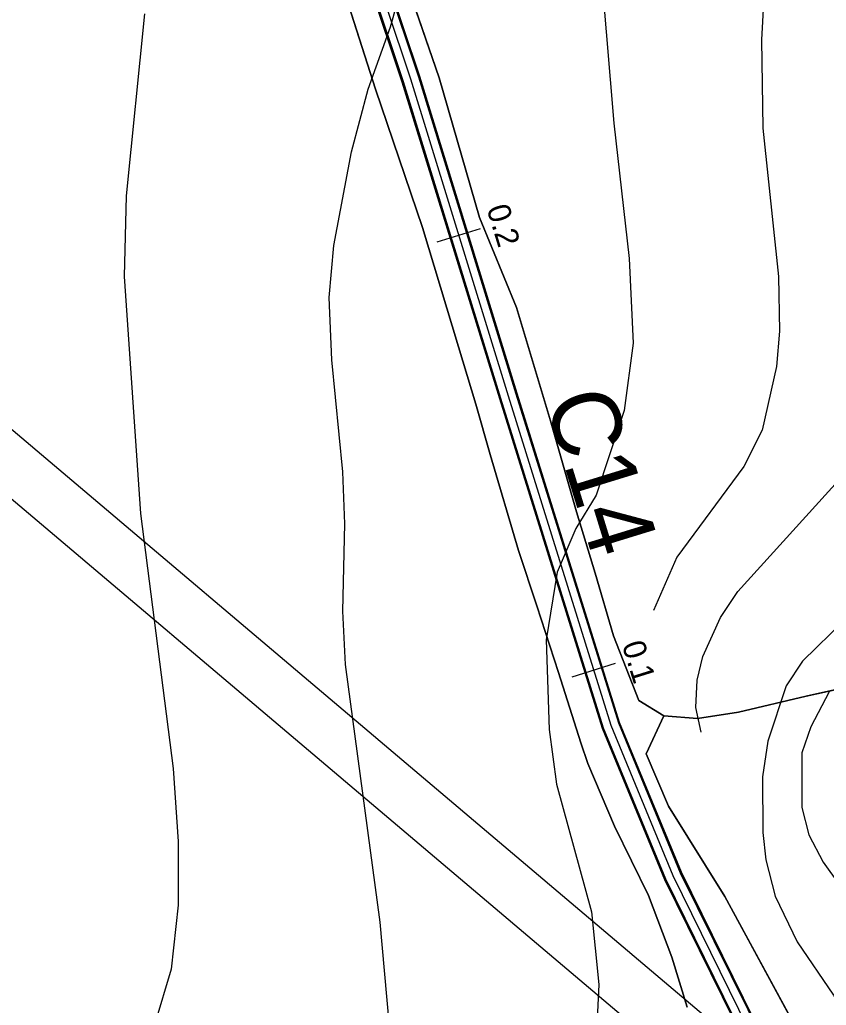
# Model space of a CAD drawing. Extents: x -662620 to -656370, y -1067090 to -1062990.
# Drawn here: x -660708.3 to -660531.2, y -1064020.6 to -1063804.1 of the extents above; entities that cross this region are included whole.
import ezdxf

# ---------------------------------------------------------------- set-up
doc = ezdxf.new("R2010")
doc.units = 0
for name, color, linetype in [('CESTA_ZABOR', 7, 'Continuous'), ('Default', 7, 'Continuous'), ('ELEK__VEDENÍ_VN_-_NADZEMNÍ', 7, 'Continuous'), ('ELEK__VEDENÍ_VVN_-_NADZEMNÍ', 7, 'Continuous'), ('ORNÁ_PŮDA_-_STÁVAJÍCÍ', 7, 'Continuous'), ('OSTATNÍ_PLOCHA_-_STÁVAJÍCÍ', 7, 'Continuous'), ('POLNÍ_CESTA_STÁVAJÍCÍ_-_KRAJ', 7, 'Continuous'), ('POLNÍ_CESTA_STÁVAJÍCÍ_-_OSA', 7, 'Continuous'), ('Popis_objektů_polních_cest_stávajících', 7, 'Continuous'), ('Trvalý_trávní_porost_-_stávající', 7, 'Continuous'), ('VRSTEVNICE_ZDŮRAZNĚNÁ', 7, 'Continuous'), ('VRSTEVNICE_ZÁKLADNÍ', 7, 'Continuous')]:
    doc.layers.add(name, color=color, linetype=linetype)

msp = doc.modelspace()

# ---------------------------------------------------------------- linework, layer by layer
at = {"layer": 'CESTA_ZABOR'}
for points in [[(-660641.89, -1063753.33), (-660620.72, -1063816.66), (-660599.33, -1063886.28), (-660576.8, -1063958.52), (-660563.25, -1063991.45), (-660541, -1064036.4), (-660545.17, -1064036.09), (-660566.44, -1063992.89), (-660580.1, -1063959.71), (-660602.67, -1063887.31), (-660624.05, -1063817.73), (-660645.21, -1063754.44), (-660641.89, -1063753.33), (-660641.89, -1063753.33)], [(-660641.89, -1063753.33), (-660620.72, -1063816.66), (-660599.33, -1063886.28), (-660576.8, -1063958.52), (-660563.25, -1063991.45), (-660541, -1064036.4), (-660545.17, -1064036.09), (-660566.44, -1063992.89), (-660580.1, -1063959.71), (-660602.67, -1063887.31), (-660624.05, -1063817.73), (-660645.21, -1063754.44)]]:
    msp.add_lwpolyline(points, dxfattribs=at)
at = {"layer": 'ELEK__VEDENÍ_VN_-_NADZEMNÍ'}
for points in [[(-660826.12, -1063795.76), (-660509.03, -1064064.22)], [(-660516.66, -1064073.17), (-660833.72, -1063804.76)]]:
    msp.add_lwpolyline(points, dxfattribs=at)
at = {"layer": 'ELEK__VEDENÍ_VVN_-_NADZEMNÍ'}
for points in [[(-661103.94, -1063560.48), (-660826.12, -1063795.76), (-660509.03, -1064064.22)], [(-659212.59, -1064402.76), (-659241.86, -1064399.78), (-659588.53, -1064364.37), (-659927.91, -1064329.98), (-660254.66, -1064303.24), (-660516.66, -1064073.17), (-660833.72, -1063804.76), (-661111.8, -1063569.65)]]:
    msp.add_lwpolyline(points, dxfattribs=at)
at = {"layer": 'ORNÁ_PŮDA_-_STÁVAJÍCÍ'}
for p, q in [((-660638.5, -1063793.19), (-660630.18, -1063819.37)), ((-660616.18, -1063816.87), (-660624.82, -1063791.76)), ((-660607.35, -1063847.54), (-660616.18, -1063816.87)), ((-660630.18, -1063819.37), (-660619.87, -1063849.72)), ((-660599.2, -1063867.29), (-660607.35, -1063847.54)), ((-660619.87, -1063849.72), (-660611.93, -1063875.98)), ((-660591.78, -1063892.18), (-660599.2, -1063867.29)), ((-660611.93, -1063875.98), (-660608.12, -1063888.55)), ((-660608.12, -1063888.55), (-660604.99, -1063899.59)), ((-660586.04, -1063912.22), (-660591.78, -1063892.18)), ((-660604.99, -1063899.59), (-660598.8, -1063920.65)), ((-660581.92, -1063925.63), (-660586.04, -1063912.22)), ((-660598.8, -1063920.65), (-660594.78, -1063932.87)), ((-660577.93, -1063939.44), (-660581.92, -1063925.63)), ((-660594.78, -1063932.87), (-660589.98, -1063947.47)), ((-660572.35, -1063953.64), (-660577.93, -1063939.44)), ((-660589.98, -1063947.47), (-660585.11, -1063962.91)), ((-660521.18, -1063949.49), (-660535.62, -1063952.7)), ((-660566.85, -1063957.02), (-660572.35, -1063953.64)), ((-660535.62, -1063952.7), (-660550.46, -1063956.21)), ((-660559.46, -1063957.55), (-660566.85, -1063957.02)), ((-660550.46, -1063956.21), (-660559.46, -1063957.55)), ((-660585.11, -1063962.91), (-660583.57, -1063967.48)), ((-660583.57, -1063967.48), (-660577.71, -1063981.23)), ((-660577.71, -1063981.23), (-660570.22, -1063996.43)), ((-660570.22, -1063996.43), (-660565.08, -1064009.97)), ((-660565.08, -1064009.97), (-660561.74, -1064020.99))]:
    msp.add_line(p, q, dxfattribs=at)
for points in [[(-660638.5, -1063793.19), (-660630.18, -1063819.37), (-660619.87, -1063849.72), (-660611.93, -1063875.98), (-660608.12, -1063888.55), (-660604.99, -1063899.59), (-660598.8, -1063920.65), (-660594.78, -1063932.87), (-660589.98, -1063947.47), (-660585.11, -1063962.91), (-660583.57, -1063967.48), (-660577.71, -1063981.23), (-660570.22, -1063996.43), (-660565.08, -1064009.97), (-660561.74, -1064020.99)], [(-660521.18, -1063949.49), (-660535.62, -1063952.7), (-660550.46, -1063956.21), (-660559.46, -1063957.55), (-660566.85, -1063957.02), (-660572.35, -1063953.64), (-660577.93, -1063939.44), (-660581.92, -1063925.63), (-660586.04, -1063912.22), (-660591.78, -1063892.18), (-660599.2, -1063867.29), (-660607.35, -1063847.54), (-660616.18, -1063816.87), (-660624.82, -1063791.76)]]:
    msp.add_lwpolyline(points, dxfattribs=at)
at = {"layer": 'OSTATNÍ_PLOCHA_-_STÁVAJÍCÍ'}
for p, q in [((-660630.18, -1063819.37), (-660638.5, -1063793.19)), ((-660630.18, -1063819.37), (-660638.5, -1063793.19)), ((-660624.82, -1063791.76), (-660616.18, -1063816.87)), ((-660624.82, -1063791.76), (-660616.18, -1063816.87)), ((-660616.18, -1063816.87), (-660607.35, -1063847.54)), ((-660616.18, -1063816.87), (-660607.35, -1063847.54)), ((-660619.87, -1063849.72), (-660630.18, -1063819.37)), ((-660619.87, -1063849.72), (-660630.18, -1063819.37)), ((-660607.35, -1063847.54), (-660599.2, -1063867.29)), ((-660607.35, -1063847.54), (-660599.2, -1063867.29)), ((-660611.93, -1063875.98), (-660619.87, -1063849.72)), ((-660611.93, -1063875.98), (-660619.87, -1063849.72)), ((-660599.2, -1063867.29), (-660591.78, -1063892.18)), ((-660599.2, -1063867.29), (-660591.78, -1063892.18)), ((-660608.12, -1063888.55), (-660611.93, -1063875.98)), ((-660608.12, -1063888.55), (-660611.93, -1063875.98)), ((-660604.99, -1063899.59), (-660608.12, -1063888.55)), ((-660604.99, -1063899.59), (-660608.12, -1063888.55)), ((-660591.78, -1063892.18), (-660586.04, -1063912.22)), ((-660591.78, -1063892.18), (-660586.04, -1063912.22)), ((-660598.8, -1063920.65), (-660604.99, -1063899.59)), ((-660598.8, -1063920.65), (-660604.99, -1063899.59)), ((-660586.04, -1063912.22), (-660581.92, -1063925.63)), ((-660586.04, -1063912.22), (-660581.92, -1063925.63)), ((-660594.78, -1063932.87), (-660598.8, -1063920.65)), ((-660594.78, -1063932.87), (-660598.8, -1063920.65)), ((-660581.92, -1063925.63), (-660577.93, -1063939.44)), ((-660581.92, -1063925.63), (-660577.93, -1063939.44)), ((-660589.98, -1063947.47), (-660594.78, -1063932.87)), ((-660589.98, -1063947.47), (-660594.78, -1063932.87)), ((-660577.93, -1063939.44), (-660572.35, -1063953.64)), ((-660577.93, -1063939.44), (-660572.35, -1063953.64)), ((-660585.11, -1063962.91), (-660589.98, -1063947.47)), ((-660585.11, -1063962.91), (-660589.98, -1063947.47)), ((-660572.35, -1063953.64), (-660566.85, -1063957.02)), ((-660572.35, -1063953.64), (-660566.85, -1063957.02)), ((-660566.85, -1063957.02), (-660570.78, -1063965.32)), ((-660566.85, -1063957.02), (-660570.78, -1063965.32)), ((-660583.57, -1063967.48), (-660585.11, -1063962.91)), ((-660583.57, -1063967.48), (-660585.11, -1063962.91)), ((-660570.78, -1063965.32), (-660565.86, -1063976.81)), ((-660570.78, -1063965.32), (-660565.86, -1063976.81)), ((-660577.71, -1063981.23), (-660583.57, -1063967.48)), ((-660577.71, -1063981.23), (-660583.57, -1063967.48)), ((-660565.86, -1063976.81), (-660553.5, -1063996.71)), ((-660565.86, -1063976.81), (-660553.5, -1063996.71)), ((-660570.22, -1063996.43), (-660577.71, -1063981.23)), ((-660570.22, -1063996.43), (-660577.71, -1063981.23)), ((-660565.08, -1064009.97), (-660570.22, -1063996.43)), ((-660565.08, -1064009.97), (-660570.22, -1063996.43)), ((-660553.5, -1063996.71), (-660534.56, -1064031.5)), ((-660553.5, -1063996.71), (-660534.56, -1064031.5)), ((-660561.74, -1064020.99), (-660565.08, -1064009.97)), ((-660561.74, -1064020.99), (-660565.08, -1064009.97))]:
    msp.add_line(p, q, dxfattribs=at)
for points in [[(-660561.74, -1064020.99), (-660565.08, -1064009.97), (-660570.22, -1063996.43), (-660577.71, -1063981.23), (-660583.57, -1063967.48), (-660585.11, -1063962.91), (-660589.98, -1063947.47), (-660594.78, -1063932.87), (-660598.8, -1063920.65), (-660604.99, -1063899.59), (-660608.12, -1063888.55), (-660611.93, -1063875.98), (-660619.87, -1063849.72), (-660630.18, -1063819.37), (-660638.5, -1063793.19)], [(-660561.74, -1064020.99), (-660565.08, -1064009.97), (-660570.22, -1063996.43), (-660577.71, -1063981.23), (-660583.57, -1063967.48), (-660585.11, -1063962.91), (-660589.98, -1063947.47), (-660594.78, -1063932.87), (-660598.8, -1063920.65), (-660604.99, -1063899.59), (-660608.12, -1063888.55), (-660611.93, -1063875.98), (-660619.87, -1063849.72), (-660630.18, -1063819.37), (-660638.5, -1063793.19)], [(-660624.82, -1063791.76), (-660616.18, -1063816.87), (-660607.35, -1063847.54), (-660599.2, -1063867.29), (-660591.78, -1063892.18), (-660586.04, -1063912.22), (-660581.92, -1063925.63), (-660577.93, -1063939.44), (-660572.35, -1063953.64), (-660566.85, -1063957.02), (-660570.78, -1063965.32), (-660565.86, -1063976.81), (-660553.5, -1063996.71), (-660534.56, -1064031.5)], [(-660624.82, -1063791.76), (-660616.18, -1063816.87), (-660607.35, -1063847.54), (-660599.2, -1063867.29), (-660591.78, -1063892.18), (-660586.04, -1063912.22), (-660581.92, -1063925.63), (-660577.93, -1063939.44), (-660572.35, -1063953.64), (-660566.85, -1063957.02), (-660570.78, -1063965.32), (-660565.86, -1063976.81), (-660553.5, -1063996.71), (-660534.56, -1064031.5)]]:
    msp.add_lwpolyline(points, dxfattribs=at)
at = {"layer": 'POLNÍ_CESTA_STÁVAJÍCÍ_-_KRAJ'}
for points in [[(-660543.88, -1064039.23), (-660566.66, -1063992.99), (-660580.33, -1063959.8), (-660602.91, -1063887.39), (-660624.29, -1063817.81), (-660645.45, -1063754.52)], [(-660540.29, -1064037.46), (-660563.02, -1063991.35), (-660576.57, -1063958.44), (-660599.09, -1063886.2), (-660620.48, -1063816.58), (-660641.66, -1063753.25)]]:
    msp.add_lwpolyline(points, dxfattribs=at)
at = {"layer": 'POLNÍ_CESTA_STÁVAJÍCÍ_-_OSA'}
for points in [[(-660542.09, -1064038.34), (-660564.84, -1063992.17), (-660578.45, -1063959.12), (-660601, -1063886.8), (-660622.39, -1063817.19), (-660643.55, -1063753.89)], [(-660616.66, -1063852.87), (-660607.1, -1063849.94)], [(-660587.03, -1063948.41), (-660577.48, -1063945.43)]]:
    msp.add_lwpolyline(points, dxfattribs=at)
at = {"layer": 'Trvalý_trávní_porost_-_stávající'}
for p, q in [((-660535.62, -1063952.7), (-660521.18, -1063949.49)), ((-660550.46, -1063956.21), (-660535.62, -1063952.7)), ((-660570.78, -1063965.32), (-660566.85, -1063957.02)), ((-660566.85, -1063957.02), (-660559.46, -1063957.55)), ((-660559.46, -1063957.55), (-660550.46, -1063956.21)), ((-660565.86, -1063976.81), (-660570.78, -1063965.32)), ((-660553.5, -1063996.71), (-660565.86, -1063976.81)), ((-660534.56, -1064031.5), (-660553.5, -1063996.71))]:
    msp.add_line(p, q, dxfattribs=at)
msp.add_lwpolyline([(-660512.65, -1064074.08), (-660534.56, -1064031.5), (-660553.5, -1063996.71), (-660565.86, -1063976.81), (-660570.78, -1063965.32), (-660566.85, -1063957.02), (-660559.46, -1063957.55), (-660550.46, -1063956.21), (-660535.62, -1063952.7), (-660521.18, -1063949.49)], dxfattribs=at)
at = {"layer": 'VRSTEVNICE_ZDŮRAZNĚNÁ'}
msp.add_lwpolyline([(-660580.31, -1063797.07), (-660577.88, -1063826.8), (-660574.45, -1063856.53), (-660573.59, -1063875.11), (-660575.59, -1063889.97), (-660581.74, -1063908.55), (-660586.17, -1063915.84), (-660590.31, -1063925.42), (-660592.74, -1063940.28), (-660592.03, -1063960.01), (-660590.46, -1063972.02), (-660582.74, -1064000.03), (-660581.16, -1064016.04), (-660581.88, -1064031.19), (-660583.88, -1064046.06), (-660591.88, -1064079.5), (-660595.46, -1064108.23)], dxfattribs=at)
at = {"layer": 'VRSTEVNICE_ZÁKLADNÍ'}
for points in [[(-660627.19, -1064024.33), (-660629.19, -1064002.32), (-660636.77, -1063945.72), (-660637.34, -1063934), (-660636.91, -1063914.84), (-660637.34, -1063903.41), (-660639.77, -1063878.82), (-660640.34, -1063865.1), (-660639.34, -1063853.67), (-660635.48, -1063833.09), (-660631.76, -1063819.36), (-660626.9, -1063805.64), (-660623.04, -1063791.92)], [(-660627.19, -1064024.33), (-660629.19, -1064002.32), (-660636.77, -1063945.72), (-660637.34, -1063934), (-660636.91, -1063914.84), (-660637.34, -1063903.41), (-660639.77, -1063878.82), (-660640.34, -1063865.1), (-660639.34, -1063853.67), (-660635.48, -1063833.09), (-660631.76, -1063819.36), (-660626.9, -1063805.64), (-660623.04, -1063791.92)], [(-660544.72, -1063795.07), (-660545.43, -1063808.5), (-660545.15, -1063827.94), (-660541.72, -1063860.53), (-660541.43, -1063872.53), (-660542.14, -1063880.25), (-660545.29, -1063894.26), (-660549.29, -1063902.26), (-660564.01, -1063922.13), (-660569.16, -1063933.85)], [(-660544.72, -1063795.07), (-660545.43, -1063808.5), (-660545.15, -1063827.94), (-660541.72, -1063860.53), (-660541.43, -1063872.53), (-660542.14, -1063880.25), (-660545.29, -1063894.26), (-660549.29, -1063902.26), (-660564.01, -1063922.13), (-660569.16, -1063933.85)], [(-660558.65, -1063960.57), (-660559.84, -1063955.18), (-660559.58, -1063949.15), (-660558.3, -1063944), (-660554.44, -1063935.43), (-660550.58, -1063929.71), (-660525.71, -1063902.26), (-660518.99, -1063890.54), (-660515.27, -1063876.82), (-660514.56, -1063870.1), (-660514.84, -1063857.38), (-660522.56, -1063805.93), (-660523.71, -1063794.49)], [(-660558.65, -1063960.57), (-660559.84, -1063955.18), (-660559.58, -1063949.15), (-660558.3, -1063944), (-660554.44, -1063935.43), (-660550.58, -1063929.71), (-660525.71, -1063902.26), (-660518.99, -1063890.54), (-660515.27, -1063876.82), (-660514.56, -1063870.1), (-660514.84, -1063857.38), (-660522.56, -1063805.93), (-660523.71, -1063794.49)], [(-660510.84, -1063802.21), (-660506.84, -1063816.5), (-660496.26, -1063843.66), (-660493.55, -1063855.1), (-660492.83, -1063862.24), (-660492.97, -1063875.11), (-660494.69, -1063886.54), (-660499.12, -1063900.84), (-660501.84, -1063906.12), (-660509.41, -1063917.27), (-660517.85, -1063926.85), (-660536.43, -1063945), (-660540, -1063950.43), (-660544, -1063962.58), (-660545.19, -1063970.39), (-660545.15, -1063982.59), (-660544.43, -1063988.6), (-660542.43, -1063996.6), (-660537.57, -1064006.61), (-660529.57, -1064018.33), (-660526.28, -1064024.33), (-660524.42, -1064030.33), (-660523.99, -1064038.48)], [(-660510.84, -1063802.21), (-660506.84, -1063816.5), (-660496.26, -1063843.66), (-660493.55, -1063855.1), (-660492.83, -1063862.24), (-660492.97, -1063875.11), (-660494.69, -1063886.54), (-660499.12, -1063900.84), (-660501.84, -1063906.12), (-660509.41, -1063917.27), (-660517.85, -1063926.85), (-660536.43, -1063945), (-660540, -1063950.43), (-660544, -1063962.58), (-660545.19, -1063970.39), (-660545.15, -1063982.59), (-660544.43, -1063988.6), (-660542.43, -1063996.6), (-660537.57, -1064006.61), (-660529.57, -1064018.33), (-660526.28, -1064024.33), (-660524.42, -1064030.33), (-660523.99, -1064038.48)], [(-660680.93, -1063802.78), (-660684.93, -1063842.8), (-660685.36, -1063860.53), (-660681.79, -1063912.56), (-660674.64, -1063968.59), (-660673.5, -1063984.59), (-660673.5, -1063998.6), (-660675.07, -1064012.61), (-660678.64, -1064024.62)], [(-660680.93, -1063802.78), (-660684.93, -1063842.8), (-660685.36, -1063860.53), (-660681.79, -1063912.56), (-660674.64, -1063968.59), (-660673.5, -1063984.59), (-660673.5, -1063998.6), (-660675.07, -1064012.61), (-660678.64, -1064024.62)], [(-660530.57, -1063951.72), (-660534.57, -1063959.44), (-660536.57, -1063965.15), (-660536.57, -1063977.16), (-660535, -1063983.16), (-660531.85, -1063989.17), (-660514.7, -1064013.18)], [(-660530.57, -1063951.72), (-660534.57, -1063959.44), (-660536.57, -1063965.15), (-660536.57, -1063977.16), (-660535, -1063983.16), (-660531.85, -1063989.17), (-660514.7, -1064013.18)]]:
    msp.add_lwpolyline(points, dxfattribs=at)

# ---------------------------------------------------------------- texts
at = {"layer": 'Default'}
for s, rotation, p in [('0.2', 287.0802, (-660605.83, -1063845.54)), ('0.1', 287.3189, (-660576.12, -1063941.39))]:
    msp.add_text(s, height=5, rotation=rotation, dxfattribs=at).set_placement(p)
at = {"layer": 'Popis_objektů_polních_cest_stávajících'}
msp.add_text('C14', height=15, rotation=287.1, dxfattribs=at).set_placement((-660593.14, -1063887.78))

doc.saveas('drawing.dxf')
